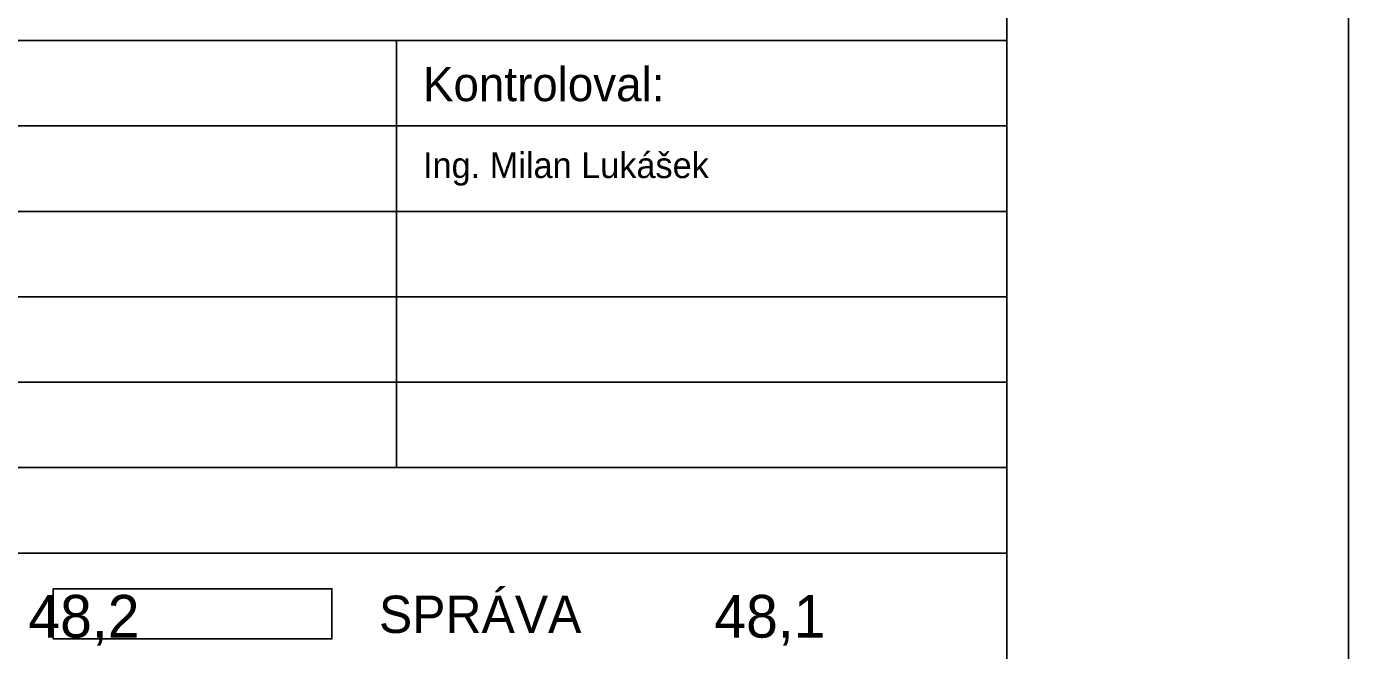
# Model space of a CAD drawing. Extents: x -1442 to 8065, y -772 to 6486.
# Drawn here: x 2542.6 to 2620, y 659.3 to 695.8 of the extents above; entities that cross this region are included whole.
import ezdxf

# ---------------------------------------------------------------- set-up
doc = ezdxf.new("R2010")
doc.units = 0
for name, color, linetype in [('Default', 7, 'Continuous'), ('Rozpiska_Logo', 7, 'Continuous'), ('Rozpiska_pole_1', 7, 'Continuous'), ('Rozpiska_pole_2', 7, 'Continuous'), ('Rozpiska_pole_4', 7, 'Continuous'), ('Rozpiska_pole_5', 7, 'Continuous'), ('Rozpiska_pole_6', 7, 'Continuous'), ('Vrstva 63', 7, 'Continuous')]:
    doc.layers.add(name, color=color, linetype=linetype)

msp = doc.modelspace()

# ---------------------------------------------------------------- linework, layer by layer
at = {"layer": 'Default'}
msp.add_line((2620, 797), (2620, 500), dxfattribs=at)
at = {"layer": 'Rozpiska_Logo'}
msp.add_lwpolyline([(2544.216, 662.91), (2560.517, 662.91), (2560.517, 659.976), (2544.216, 659.976)], close=True, dxfattribs=at)
at = {"layer": 'Rozpiska_pole_1'}
msp.add_lwpolyline([(2430, 780), (2600, 780), (2600, 515), (2430, 515)], close=True, dxfattribs=at)
at = {"layer": 'Rozpiska_pole_2'}
msp.add_lwpolyline([(2600, 735), (2536.65, 735), (2536.65, 695), (2600, 695)], close=True, dxfattribs=at)
at = {"layer": 'Rozpiska_pole_4'}
for p, q in [((2564.3, 670), (2564.3, 695)), ((2430, 690), (2600, 690)), ((2430, 685), (2600, 685)), ((2430, 680), (2600, 680)), ((2430, 675), (2600, 675))]:
    msp.add_line(p, q, dxfattribs=at)
msp.add_lwpolyline([(2430, 695), (2600, 695), (2600, 670), (2430, 670)], close=True, dxfattribs=at)
at = {"layer": 'Rozpiska_pole_5'}
msp.add_lwpolyline([(2430, 665), (2600, 665), (2600, 645), (2430, 645)], close=True, dxfattribs=at)
at = {"layer": 'Vrstva 63'}
msp.add_lwpolyline([(2200, 500), (2620, 500), (2620, 797), (2200, 797)], close=True, dxfattribs=at)

# ---------------------------------------------------------------- texts
for s, p in [('48,2', (2542.752, 660.051)), ('48,1', (2582.889, 660.051))]:
    msp.add_text(s, height=2.5).set_placement(p)
at = {"layer": 'Rozpiska_pole_4'}
for s, height, p in [('Kontroloval:', 2, (2565.846, 691.453)), ('Ing. Milan Lukášek', 1.5, (2565.846, 686.953))]:
    msp.add_text(s, height=height, dxfattribs=at).set_placement(p)
at = {"layer": 'Rozpiska_pole_6'}
msp.add_text('SPRÁVA', height=2.1832, dxfattribs=at).set_placement((2563.268, 660.325))

doc.saveas('drawing.dxf')
